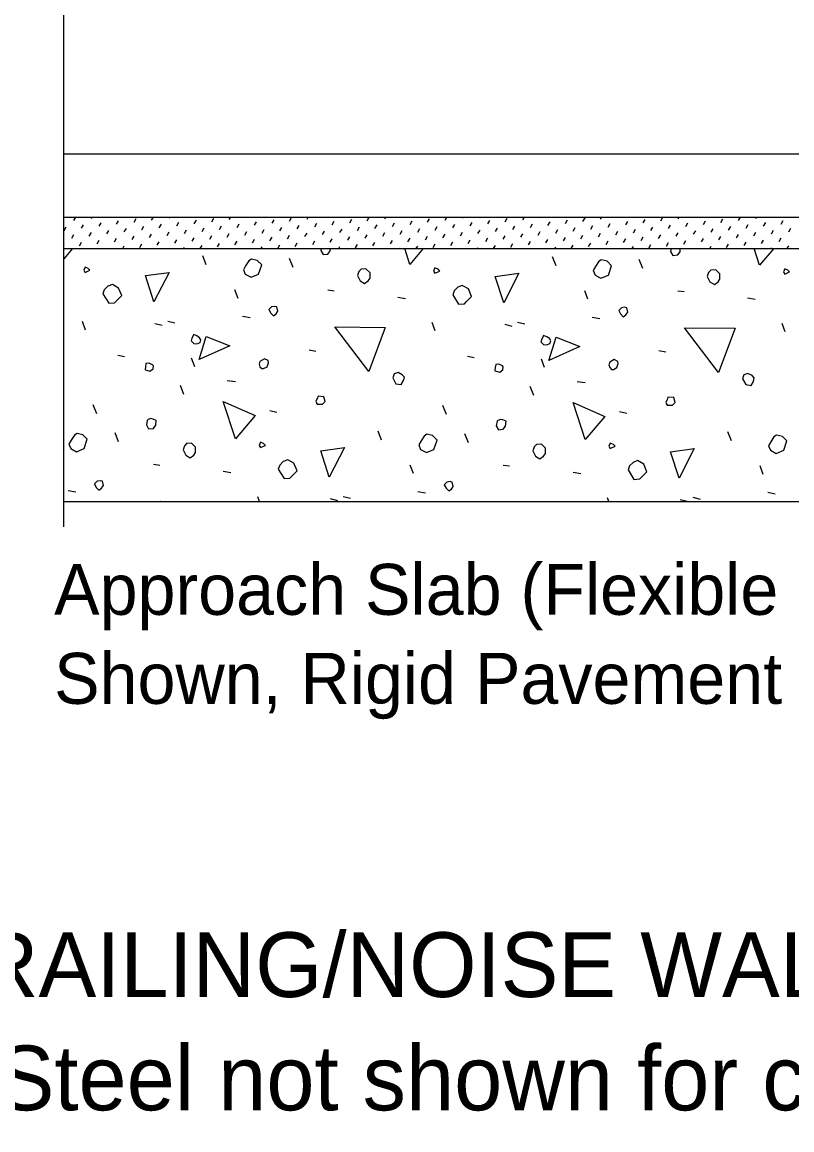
# Model space of a CAD drawing. Extents: x 120631.6 to 120706.2, y 120663.5 to 120716.4.
# Drawn here: x 120654.131 to 120657.173, y 120690.936 to 120695.317 of the extents above; entities that cross this region are included whole.
import ezdxf

# ---------------------------------------------------------------- set-up
doc = ezdxf.new("R2010")
doc.units = 0
for name, color, linetype in [('Dimension', 7, 'Continuous'), ('Miscellaneous', 7, 'Continuous'), ('TrafBarrierConc', 7, 'Continuous')]:
    doc.layers.add(name, color=color, linetype=linetype)

msp = doc.modelspace()

# ---------------------------------------------------------------- linework, layer by layer
at = {"layer": 'Dimension'}
msp.add_lwpolyline([(120654.2962, 120693.3211), (120654.2962, 120695.4418), (120654.1928, 120695.4418), (120654.2962, 120695.4868), (120654.3995, 120695.5318), (120654.2962, 120695.5318), (120654.2962, 120696.2127)], dxfattribs=at)
at = {"layer": 'Miscellaneous'}
for p, q in [((120654.3357, 120694.532), (120654.3438, 120694.546)), ((120654.4049, 120694.5401), (120654.4083, 120694.546)), ((120654.4354, 120694.5095), (120654.4435, 120694.5235)), ((120654.5046, 120694.5176), (120654.5127, 120694.5316)), ((120654.5737, 120694.5257), (120654.5818, 120694.5397)), ((120654.6429, 120694.5338), (120654.6499, 120694.546)), ((120654.7121, 120694.5419), (120654.7144, 120694.546)), ((120654.7426, 120694.5114), (120654.7507, 120694.5254)), ((120654.8118, 120694.5195), (120654.8199, 120694.5335)), ((120654.8809, 120694.5276), (120654.889, 120694.5416)), ((120654.9501, 120694.5357), (120654.956, 120694.546)), ((120654.9806, 120694.5052), (120654.9887, 120694.5192)), ((120655.0193, 120694.5438), (120655.0205, 120694.546)), ((120655.0498, 120694.5133), (120655.0579, 120694.5273)), ((120655.1189, 120694.5214), (120655.127, 120694.5354)), ((120655.1881, 120694.5295), (120655.1962, 120694.5435)), ((120655.2573, 120694.5376), (120655.2621, 120694.546)), ((120655.2878, 120694.5071), (120655.2959, 120694.5211)), ((120655.3264, 120694.5457), (120655.3266, 120694.546)), ((120655.357, 120694.5152), (120655.3651, 120694.5292)), ((120655.4261, 120694.5233), (120655.4342, 120694.5373)), ((120655.4953, 120694.5314), (120655.5034, 120694.5454)), ((120655.5645, 120694.5395), (120655.5682, 120694.546)), ((120655.595, 120694.5089), (120655.6031, 120694.5229)), ((120655.6642, 120694.517), (120655.6723, 120694.531)), ((120655.7333, 120694.5251), (120655.7414, 120694.5391)), ((120655.8025, 120694.5333), (120655.8099, 120694.546)), ((120655.8716, 120694.5414), (120655.8743, 120694.546)), ((120655.9022, 120694.5108), (120655.9103, 120694.5248)), ((120655.9713, 120694.5189), (120655.9794, 120694.5329)), ((120656.0405, 120694.527), (120656.0486, 120694.541)), ((120656.1097, 120694.5351), (120656.116, 120694.546)), ((120656.1402, 120694.5046), (120656.1483, 120694.5186)), ((120656.1788, 120694.5432), (120656.1804, 120694.546)), ((120656.2094, 120694.5127), (120656.2175, 120694.5267)), ((120656.2785, 120694.5208), (120656.2866, 120694.5348)), ((120656.3477, 120694.5289), (120656.3558, 120694.5429)), ((120656.4169, 120694.537), (120656.4221, 120694.546)), ((120656.4474, 120694.5065), (120656.4555, 120694.5205)), ((120656.486, 120694.5451), (120656.4865, 120694.546)), ((120656.5165, 120694.5146), (120656.5247, 120694.5286)), ((120656.5857, 120694.5227), (120656.5938, 120694.5367)), ((120656.6549, 120694.5308), (120656.663, 120694.5448)), ((120656.724, 120694.5389), (120656.7282, 120694.546)), ((120656.7546, 120694.5084), (120656.7627, 120694.5224)), ((120656.8237, 120694.5165), (120656.8318, 120694.5305)), ((120656.8929, 120694.5246), (120656.901, 120694.5386)), ((120656.9621, 120694.5327), (120656.9698, 120694.546)), ((120657.0312, 120694.5408), (120657.0343, 120694.546)), ((120657.0618, 120694.5102), (120657.0699, 120694.5242)), ((120657.1309, 120694.5183), (120657.139, 120694.5323)), ((120654.2971, 120694.4933), (120654.3052, 120694.5073)), ((120654.3276, 120694.4628), (120654.3357, 120694.4768)), ((120654.3662, 120694.5014), (120654.3743, 120694.5154)), ((120654.3968, 120694.4709), (120654.4049, 120694.4849)), ((120654.4659, 120694.479), (120654.474, 120694.493)), ((120654.5351, 120694.4871), (120654.5432, 120694.5011)), ((120654.6043, 120694.4952), (120654.6124, 120694.5092)), ((120654.6348, 120694.4647), (120654.6429, 120694.4787)), ((120654.6734, 120694.5033), (120654.6815, 120694.5173)), ((120654.704, 120694.4728), (120654.7121, 120694.4868)), ((120654.7731, 120694.4809), (120654.7812, 120694.4949)), ((120654.8423, 120694.489), (120654.8504, 120694.503)), ((120654.9115, 120694.4971), (120654.9196, 120694.5111)), ((120654.942, 120694.4666), (120654.9501, 120694.4806)), ((120655.0111, 120694.4747), (120655.0193, 120694.4887)), ((120655.0803, 120694.4828), (120655.0884, 120694.4968)), ((120655.1495, 120694.4909), (120655.1576, 120694.5049)), ((120655.18, 120694.4603), (120655.1881, 120694.4743)), ((120655.2186, 120694.499), (120655.2267, 120694.513)), ((120655.2492, 120694.4684), (120655.2573, 120694.4824)), ((120655.3183, 120694.4765), (120655.3264, 120694.4905)), ((120655.3875, 120694.4846), (120655.3956, 120694.4986)), ((120655.4567, 120694.4927), (120655.4648, 120694.5067)), ((120655.4872, 120694.4622), (120655.4953, 120694.4762)), ((120655.5258, 120694.5008), (120655.5339, 120694.5148)), ((120655.5564, 120694.4703), (120655.5645, 120694.4843)), ((120655.6255, 120694.4784), (120655.6336, 120694.4924)), ((120655.6947, 120694.4865), (120655.7028, 120694.5005)), ((120655.7638, 120694.4946), (120655.772, 120694.5086)), ((120655.7944, 120694.4641), (120655.8025, 120694.4781)), ((120655.833, 120694.5027), (120655.8411, 120694.5167)), ((120655.8635, 120694.4722), (120655.8716, 120694.4862)), ((120655.9327, 120694.4803), (120655.9408, 120694.4943)), ((120656.0019, 120694.4884), (120656.01, 120694.5024)), ((120656.071, 120694.4965), (120656.0791, 120694.5105)), ((120656.1016, 120694.466), (120656.1097, 120694.48)), ((120656.1707, 120694.4741), (120656.1788, 120694.4881)), ((120656.2399, 120694.4822), (120656.248, 120694.4962)), ((120656.3091, 120694.4903), (120656.3172, 120694.5043)), ((120656.3782, 120694.4984), (120656.3863, 120694.5124)), ((120656.4088, 120694.4678), (120656.4169, 120694.4818)), ((120656.4779, 120694.4759), (120656.486, 120694.4899)), ((120656.5471, 120694.484), (120656.5552, 120694.498)), ((120656.6162, 120694.4922), (120656.6243, 120694.5061)), ((120656.6468, 120694.4616), (120656.6549, 120694.4756)), ((120656.6854, 120694.5003), (120656.6935, 120694.5142)), ((120656.7159, 120694.4697), (120656.724, 120694.4837)), ((120656.7851, 120694.4778), (120656.7932, 120694.4918)), ((120656.8543, 120694.4859), (120656.8624, 120694.4999)), ((120656.9234, 120694.494), (120656.9315, 120694.508)), ((120656.954, 120694.4635), (120656.9621, 120694.4775)), ((120656.9926, 120694.5021), (120657.0007, 120694.5161)), ((120657.0231, 120694.4716), (120657.0312, 120694.4856)), ((120657.0923, 120694.4797), (120657.1004, 120694.4937)), ((120657.1615, 120694.4878), (120657.1696, 120694.5018)), ((120654.2962, 120694.4366), (120654.2971, 120694.4382)), ((120654.3581, 120694.4323), (120654.3662, 120694.4463)), ((120654.4273, 120694.4404), (120654.4354, 120694.4544)), ((120654.4965, 120694.4485), (120654.5046, 120694.4625)), ((120654.5288, 120694.421), (120654.5351, 120694.4319)), ((120654.5656, 120694.4566), (120654.5737, 120694.4706)), ((120654.5962, 120694.426), (120654.6043, 120694.44)), ((120654.6653, 120694.4341), (120654.6734, 120694.4481)), ((120654.7345, 120694.4422), (120654.7426, 120694.4562)), ((120654.8037, 120694.4504), (120654.8118, 120694.4643)), ((120654.8349, 120694.421), (120654.8423, 120694.4338)), ((120654.8728, 120694.4585), (120654.8809, 120694.4724)), ((120654.9034, 120694.4279), (120654.9115, 120694.4419)), ((120654.9725, 120694.436), (120654.9806, 120694.45)), ((120655.0417, 120694.4441), (120655.0498, 120694.4581)), ((120655.1108, 120694.4522), (120655.1189, 120694.4662)), ((120655.1414, 120694.4217), (120655.1495, 120694.4357)), ((120655.2105, 120694.4298), (120655.2186, 120694.4438)), ((120655.2797, 120694.4379), (120655.2878, 120694.4519)), ((120655.3489, 120694.446), (120655.357, 120694.46)), ((120655.418, 120694.4541), (120655.4261, 120694.4681)), ((120655.4486, 120694.4236), (120655.4567, 120694.4376)), ((120655.5177, 120694.4317), (120655.5258, 120694.4457)), ((120655.5869, 120694.4398), (120655.595, 120694.4538)), ((120655.6561, 120694.4479), (120655.6642, 120694.4619)), ((120655.6887, 120694.421), (120655.6947, 120694.4313)), ((120655.7252, 120694.456), (120655.7333, 120694.47)), ((120655.7557, 120694.4255), (120655.7638, 120694.4395)), ((120655.8249, 120694.4336), (120655.833, 120694.4476)), ((120655.8941, 120694.4417), (120655.9022, 120694.4557)), ((120655.9632, 120694.4498), (120655.9713, 120694.4638)), ((120655.9948, 120694.421), (120656.0019, 120694.4332)), ((120656.0324, 120694.4579), (120656.0405, 120694.4719)), ((120656.0629, 120694.4273), (120656.071, 120694.4413)), ((120656.1321, 120694.4354), (120656.1402, 120694.4494)), ((120656.2013, 120694.4435), (120656.2094, 120694.4575)), ((120656.2704, 120694.4516), (120656.2785, 120694.4656)), ((120656.301, 120694.4211), (120656.3091, 120694.4351)), ((120656.3396, 120694.4597), (120656.3477, 120694.4737)), ((120656.3701, 120694.4292), (120656.3782, 120694.4432)), ((120656.4393, 120694.4373), (120656.4474, 120694.4513)), ((120656.5084, 120694.4454), (120656.5165, 120694.4594)), ((120656.5776, 120694.4535), (120656.5857, 120694.4675)), ((120656.6081, 120694.423), (120656.6162, 120694.437)), ((120656.6773, 120694.4311), (120656.6854, 120694.4451)), ((120656.7465, 120694.4392), (120656.7546, 120694.4532)), ((120656.8156, 120694.4473), (120656.8237, 120694.4613)), ((120656.8486, 120694.421), (120656.8543, 120694.4308)), ((120656.8848, 120694.4554), (120656.8929, 120694.4694)), ((120656.9153, 120694.4249), (120656.9234, 120694.4389)), ((120656.9845, 120694.433), (120656.9926, 120694.447)), ((120657.0537, 120694.4411), (120657.0618, 120694.4551)), ((120657.1228, 120694.4492), (120657.1309, 120694.4632)), ((120657.1547, 120694.421), (120657.1615, 120694.4326)), ((120654.4643, 120694.421), (120654.4659, 120694.4238)), ((120654.7704, 120694.421), (120654.7731, 120694.4257)), ((120654.8592, 120694.357), (120654.845, 120694.3923)), ((120655.0765, 120694.421), (120655.0803, 120694.4276)), ((120655.3181, 120694.421), (120655.3183, 120694.4214)), ((120655.3826, 120694.421), (120655.3875, 120694.4295)), ((120655.6242, 120694.421), (120655.6255, 120694.4232)), ((120655.9303, 120694.421), (120655.9327, 120694.4251)), ((120656.2415, 120694.3534), (120656.2274, 120694.3888)), ((120656.2364, 120694.421), (120656.2399, 120694.427)), ((120656.5425, 120694.421), (120656.5471, 120694.4289)), ((120656.7841, 120694.421), (120656.7851, 120694.4227)), ((120657.0902, 120694.421), (120657.0923, 120694.4245)), ((120655.2021, 120694.3464), (120655.188, 120694.3817)), ((120656.5845, 120694.3428), (120656.5704, 120694.3782)), ((120654.9847, 120694.2244), (120654.9723, 120694.258)), ((120655.34, 120694.258), (120655.3647, 120694.2544)), ((120655.6158, 120694.2297), (120655.6458, 120694.2244)), ((120656.3671, 120694.2208), (120656.3547, 120694.2544)), ((120656.7224, 120694.2544), (120656.7471, 120694.2509)), ((120656.9982, 120694.2261), (120657.0282, 120694.2208)), ((120654.3819, 120694.0989), (120654.3695, 120694.1325)), ((120654.6559, 120694.1254), (120654.6841, 120694.1183)), ((120654.7071, 120694.1342), (120654.7354, 120694.1272)), ((120655.0023, 120694.1537), (120655.0324, 120694.1484)), ((120655.7642, 120694.0953), (120655.7519, 120694.1289)), ((120656.0895, 120694.1307), (120656.1178, 120694.1236)), ((120656.3847, 120694.1501), (120656.4148, 120694.1448)), ((120657.1466, 120694.0918), (120657.1343, 120694.1254)), ((120656.0383, 120694.1219), (120656.0665, 120694.1148)), ((120654.5091, 120693.9999), (120654.5357, 120693.9946)), ((120655.2657, 120694.0211), (120655.2923, 120694.0158)), ((120655.8915, 120693.9963), (120655.918, 120693.991)), ((120656.6481, 120694.0176), (120656.6746, 120694.0122)), ((120654.8132, 120693.9539), (120654.8008, 120693.9875)), ((120656.1956, 120693.9504), (120656.1832, 120693.984)), ((120654.7708, 120693.8443), (120654.7566, 120693.8797)), ((120654.9422, 120693.8991), (120654.9741, 120693.8956)), ((120656.1532, 120693.8408), (120656.139, 120693.8761)), ((120656.3246, 120693.8956), (120656.3565, 120693.892)), ((120654.426, 120693.7683), (120654.4119, 120693.8037)), ((120655.1102, 120693.7807), (120655.1385, 120693.7736)), ((120655.8084, 120693.7648), (120655.7943, 120693.8001)), ((120656.4926, 120693.7771), (120656.5209, 120693.7701)), ((120654.5127, 120693.6569), (120654.4985, 120693.6923)), ((120655.5521, 120693.664), (120655.538, 120693.6994)), ((120655.8951, 120693.6534), (120655.8809, 120693.6887)), ((120656.9345, 120693.6605), (120656.9204, 120693.6958)), ((120654.6506, 120693.5685), (120654.6753, 120693.565)), ((120655.6776, 120693.5314), (120655.6653, 120693.565)), ((120656.0329, 120693.565), (120656.0577, 120693.5615)), ((120657.06, 120693.5279), (120657.0476, 120693.5615)), ((120654.9263, 120693.5403), (120654.9564, 120693.535)), ((120656.3087, 120693.5367), (120656.3388, 120693.5314)), ((120654.3129, 120693.4642), (120654.343, 120693.4589)), ((120655.0693, 120693.421), (120655.0624, 120693.4395)), ((120655.3488, 120693.4324), (120655.3771, 120693.4254)), ((120655.4001, 120693.4413), (120655.4284, 120693.4342)), ((120655.6953, 120693.4607), (120655.7254, 120693.4554)), ((120656.4503, 120693.421), (120656.4448, 120693.436)), ((120656.7312, 120693.4289), (120656.7595, 120693.4218)), ((120656.7825, 120693.4377), (120656.8108, 120693.4307)), ((120657.0777, 120693.4572), (120657.1078, 120693.4519))]:
    msp.add_line(p, q, dxfattribs=at)
for points in [[(120654.3308, 120694.421), (120654.2962, 120694.3801)], [(120655.3117, 120694.4135), (120655.3205, 120694.3976), (120655.34, 120694.3994), (120655.3488, 120694.4118), (120655.3497, 120694.421)], [(120655.3132, 120694.421), (120655.3117, 120694.4135)], [(120655.6635, 120694.3587), (120655.6432, 120694.421)], [(120655.7162, 120694.421), (120655.6635, 120694.3587)], [(120656.6941, 120694.41), (120656.7029, 120694.3941), (120656.7224, 120694.3959), (120656.7312, 120694.4082), (120656.7324, 120694.421)], [(120656.6963, 120694.421), (120656.6941, 120694.41)], [(120657.0459, 120694.3552), (120657.0245, 120694.421)], [(120657.1016, 120694.421), (120657.0459, 120694.3552)], [(120654.3801, 120694.3269), (120654.3995, 120694.3358), (120654.3925, 120694.3428), (120654.3801, 120694.3481), (120654.3748, 120694.3358), (120654.3801, 120694.3269)], [(120655.0129, 120694.3198), (120655.0359, 120694.3075), (120655.066, 120694.3198), (120655.0784, 120694.357), (120655.0607, 120694.3746), (120655.0377, 120694.3799), (120655.0271, 120694.3729), (120655.0147, 120694.3534), (120655.0059, 120694.3375), (120655.0129, 120694.3198)], [(120655.7625, 120694.3234), (120655.7819, 120694.3322), (120655.7749, 120694.3393), (120655.7625, 120694.3446), (120655.7572, 120694.3322), (120655.7625, 120694.3234)], [(120656.3953, 120694.3163), (120656.4183, 120694.3039), (120656.4484, 120694.3163), (120656.4607, 120694.3534), (120656.4431, 120694.3711), (120656.4201, 120694.3764), (120656.4095, 120694.3693), (120656.3971, 120694.3499), (120656.3883, 120694.334), (120656.3953, 120694.3163)], [(120654.6523, 120694.2102), (120654.6187, 120694.3145), (120654.7124, 120694.3269), (120654.6523, 120694.2102)], [(120655.4567, 120694.3145), (120655.4673, 120694.2933), (120655.4849, 120694.2827), (120655.4991, 120694.2933), (120655.5062, 120694.3039), (120655.5062, 120694.3251), (120655.4902, 120694.3411), (120655.4708, 120694.3393), (120655.462, 120694.3304), (120655.4567, 120694.3145)], [(120656.0347, 120694.2067), (120656.0011, 120694.311), (120656.0948, 120694.3234), (120656.0347, 120694.2067)], [(120656.8391, 120694.311), (120656.8497, 120694.2898), (120656.8673, 120694.2792), (120656.8815, 120694.2898), (120656.8885, 120694.3004), (120656.8885, 120694.3216), (120656.8726, 120694.3375), (120656.8532, 120694.3358), (120656.8444, 120694.3269), (120656.8391, 120694.311)], [(120657.1449, 120694.3198), (120657.1643, 120694.3287), (120657.1572, 120694.3358), (120657.1449, 120694.3411), (120657.1396, 120694.3287), (120657.1449, 120694.3198)], [(120654.4508, 120694.2421), (120654.4738, 120694.2049), (120654.4968, 120694.2067), (120654.5056, 120694.2155), (120654.525, 120694.235), (120654.5127, 120694.265), (120654.4879, 120694.2792), (120654.4702, 120694.2721), (120654.4561, 120694.258), (120654.4508, 120694.2421)], [(120655.8332, 120694.2385), (120655.8562, 120694.2014), (120655.8792, 120694.2032), (120655.888, 120694.212), (120655.9074, 120694.2315), (120655.8951, 120694.2615), (120655.8703, 120694.2756), (120655.8526, 120694.2686), (120655.8385, 120694.2544), (120655.8332, 120694.2385)], [(120655.1137, 120694.166), (120655.1243, 120694.1554), (120655.1349, 120694.1625), (120655.142, 120694.1731), (120655.1385, 120694.1908), (120655.1296, 120694.1926), (120655.1172, 120694.1908), (120655.1066, 120694.1802), (120655.1137, 120694.166)], [(120656.4961, 120694.1625), (120656.5067, 120694.1519), (120656.5173, 120694.159), (120656.5244, 120694.1696), (120656.5209, 120694.1873), (120656.512, 120694.189), (120656.4996, 120694.1873), (120656.489, 120694.1767), (120656.4961, 120694.1625)], [(120654.8097, 120694.0458), (120654.822, 120694.0441), (120654.8344, 120694.0494), (120654.8379, 120694.06), (120654.8326, 120694.0688), (120654.822, 120694.0759), (120654.8097, 120694.0812), (120654.8026, 120694.067), (120654.799, 120694.0564), (120654.8097, 120694.0458)], [(120655.5009, 120693.9345), (120655.3665, 120694.1112), (120655.5663, 120694.1095), (120655.5009, 120693.9345)], [(120656.8832, 120693.9309), (120656.7489, 120694.1077), (120656.9487, 120694.1059), (120656.8832, 120693.9309)], [(120654.8309, 120693.9822), (120654.8592, 120694.0741), (120654.9528, 120694.037), (120654.8309, 120693.9822)], [(120656.192, 120694.0423), (120656.2044, 120694.0405), (120656.2168, 120694.0458), (120656.2203, 120694.0564), (120656.215, 120694.0653), (120656.2044, 120694.0724), (120656.192, 120694.0777), (120656.185, 120694.0635), (120656.1814, 120694.0529), (120656.192, 120694.0423)], [(120656.2133, 120693.9787), (120656.2415, 120694.0706), (120656.3352, 120694.0335), (120656.2133, 120693.9787)], [(120654.617, 120693.9415), (120654.6364, 120693.9362), (120654.6488, 120693.9451), (120654.6506, 120693.9574), (120654.647, 120693.961), (120654.6329, 120693.9681), (120654.6205, 120693.9663), (120654.6187, 120693.9539), (120654.617, 120693.9415)], [(120655.0784, 120693.9468), (120655.0854, 120693.9468), (120655.0996, 120693.9539), (120655.1049, 120693.9698), (120655.1031, 120693.9787), (120655.089, 120693.9857), (120655.0713, 120693.9751), (120655.0677, 120693.9645), (120655.0713, 120693.9539), (120655.0784, 120693.9468)], [(120655.9994, 120693.938), (120656.0188, 120693.9327), (120656.0312, 120693.9415), (120656.0329, 120693.9539), (120656.0294, 120693.9574), (120656.0153, 120693.9645), (120656.0029, 120693.9628), (120656.0011, 120693.9504), (120655.9994, 120693.938)], [(120656.4607, 120693.9433), (120656.4678, 120693.9433), (120656.482, 120693.9504), (120656.4873, 120693.9663), (120656.4855, 120693.9751), (120656.4714, 120693.9822), (120656.4537, 120693.9716), (120656.4501, 120693.961), (120656.4537, 120693.9504), (120656.4607, 120693.9433)], [(120655.5998, 120693.9026), (120655.6087, 120693.8867), (120655.6299, 120693.8832), (120655.6387, 120693.8991), (120655.6423, 120693.9133), (120655.6334, 120693.9221), (120655.6175, 120693.9309), (120655.6016, 120693.9256), (120655.5963, 120693.9097), (120655.5998, 120693.9026)], [(120656.9822, 120693.8991), (120656.9911, 120693.8832), (120657.0123, 120693.8797), (120657.0211, 120693.8956), (120657.0247, 120693.9097), (120657.0158, 120693.9186), (120656.9999, 120693.9274), (120656.984, 120693.9221), (120656.9787, 120693.9062), (120656.9822, 120693.8991)], [(120655.2976, 120693.8054), (120655.3188, 120693.8054), (120655.3294, 120693.816), (120655.3241, 120693.8355), (120655.3011, 120693.8372), (120655.2976, 120693.8266), (120655.2923, 120693.8178), (120655.2976, 120693.8054), (120655.294, 120693.809)], [(120656.68, 120693.8019), (120656.7012, 120693.8019), (120656.7118, 120693.8125), (120656.7065, 120693.8319), (120656.6835, 120693.8337), (120656.68, 120693.8231), (120656.6746, 120693.8143), (120656.68, 120693.8019), (120656.6764, 120693.8054)], [(120654.9741, 120693.6693), (120654.9263, 120693.816), (120655.0518, 120693.7612), (120654.9741, 120693.6693)], [(120656.3565, 120693.6658), (120656.3087, 120693.8125), (120656.4342, 120693.7577), (120656.3565, 120693.6658)], [(120654.6223, 120693.7241), (120654.6311, 120693.7082), (120654.6506, 120693.71), (120654.6594, 120693.7223), (120654.6612, 120693.7418), (120654.6488, 120693.7471), (120654.6399, 120693.7489), (120654.6293, 120693.7453), (120654.6258, 120693.7418), (120654.6223, 120693.7241)], [(120656.0047, 120693.7206), (120656.0135, 120693.7047), (120656.0329, 120693.7064), (120656.0418, 120693.7188), (120656.0436, 120693.7382), (120656.0312, 120693.7435), (120656.0223, 120693.7453), (120656.0117, 120693.7418), (120656.0082, 120693.7382), (120656.0047, 120693.7206)], [(120654.3235, 120693.6304), (120654.3465, 120693.618), (120654.3766, 120693.6304), (120654.3889, 120693.6675), (120654.3712, 120693.6852), (120654.3483, 120693.6905), (120654.3377, 120693.6834), (120654.3253, 120693.664), (120654.3164, 120693.6481), (120654.3235, 120693.6304)], [(120655.7059, 120693.6269), (120655.7289, 120693.6145), (120655.7589, 120693.6269), (120655.7713, 120693.664), (120655.7536, 120693.6817), (120655.7307, 120693.687), (120655.7201, 120693.6799), (120655.7077, 120693.6605), (120655.6988, 120693.6446), (120655.7059, 120693.6269)], [(120654.7672, 120693.6251), (120654.7778, 120693.6039), (120654.7955, 120693.5933), (120654.8097, 120693.6039), (120654.8167, 120693.6145), (120654.8167, 120693.6357), (120654.8008, 120693.6516), (120654.7814, 120693.6499), (120654.7725, 120693.641), (120654.7672, 120693.6251)], [(120655.0731, 120693.6339), (120655.0925, 120693.6428), (120655.0854, 120693.6499), (120655.0731, 120693.6552), (120655.0677, 120693.6428), (120655.0731, 120693.6339)], [(120656.1496, 120693.6216), (120656.1602, 120693.6004), (120656.1779, 120693.5898), (120656.192, 120693.6004), (120656.1991, 120693.611), (120656.1991, 120693.6322), (120656.1832, 120693.6481), (120656.1638, 120693.6463), (120656.1549, 120693.6375), (120656.1496, 120693.6216)], [(120656.4554, 120693.6304), (120656.4749, 120693.6392), (120656.4678, 120693.6463), (120656.4554, 120693.6516), (120656.4501, 120693.6392), (120656.4554, 120693.6304)], [(120657.0883, 120693.6233), (120657.1113, 120693.611), (120657.1413, 120693.6233), (120657.1537, 120693.6605), (120657.136, 120693.6781), (120657.1131, 120693.6834), (120657.1024, 120693.6764), (120657.0901, 120693.6569), (120657.0812, 120693.641), (120657.0883, 120693.6233)], [(120655.3453, 120693.5173), (120655.3117, 120693.6216), (120655.4054, 120693.6339), (120655.3453, 120693.5173)], [(120656.7277, 120693.5137), (120656.6941, 120693.618), (120656.7878, 120693.6304), (120656.7277, 120693.5137)], [(120655.1438, 120693.5491), (120655.1667, 120693.512), (120655.1897, 120693.5137), (120655.1986, 120693.5226), (120655.218, 120693.542), (120655.2056, 120693.5721), (120655.1809, 120693.5862), (120655.1632, 120693.5791), (120655.1491, 120693.565), (120655.1438, 120693.5491)], [(120656.5262, 120693.5456), (120656.5491, 120693.5084), (120656.5721, 120693.5102), (120656.581, 120693.519), (120656.6004, 120693.5385), (120656.588, 120693.5685), (120656.5633, 120693.5827), (120656.5456, 120693.5756), (120656.5315, 120693.5615), (120656.5262, 120693.5456)], [(120654.4243, 120693.4766), (120654.4349, 120693.466), (120654.4455, 120693.4731), (120654.4526, 120693.4837), (120654.449, 120693.5014), (120654.4402, 120693.5031), (120654.4278, 120693.5014), (120654.4172, 120693.4908), (120654.4243, 120693.4766)], [(120655.8067, 120693.4731), (120655.8173, 120693.4625), (120655.8279, 120693.4695), (120655.835, 120693.4802), (120655.8314, 120693.4978), (120655.8226, 120693.4996), (120655.8102, 120693.4978), (120655.7996, 120693.4872), (120655.8067, 120693.4731)], [(120654.6777, 120693.421), (120654.6771, 120693.4218), (120654.7682, 120693.421)]]:
    msp.add_lwpolyline(points, dxfattribs=at)
at = {"layer": 'TrafBarrierConc'}
for p, q in [((120654.2962, 120694.7961), (120670.1273, 120694.7961)), ((120654.2962, 120694.5461), (120670.1273, 120694.5461)), ((120654.2962, 120694.421), (120670.1273, 120694.421)), ((120654.2962, 120693.4211), (120670.1273, 120693.4211))]:
    msp.add_line(p, q, dxfattribs=at)

# ---------------------------------------------------------------- texts
at = {"layer": 'Dimension'}
for s, height, p in [('Approach Slab (Flexible Pavement Approach Slab ', 0.2016, (120654.2576, 120692.9727)), ('Shown, Rigid Pavement Approach Slab Similar)', 0.2016, (120654.2576, 120692.6207)), ('ELEVATION OF INSIDE FACE OF RAILING/NOISE WALL (BRIDGE MOUNTED RAILING/NOISE WALL SHOWN, ', 0.256001, (120641.547, 120691.4611)), ('WALL OR FOOTING MOUNTED RAILING/NOISE WALL SIMILAR) (Reinforcing Steel not shown for clarity)', 0.256001, (120641.7426, 120691.0131))]:
    msp.add_text(s, height=height, dxfattribs=at).set_placement(p)

doc.saveas('drawing.dxf')
